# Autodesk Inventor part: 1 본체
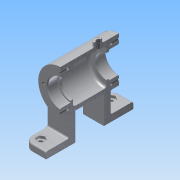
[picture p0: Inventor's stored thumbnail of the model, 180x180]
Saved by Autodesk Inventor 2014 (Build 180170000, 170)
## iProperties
Created: 2017-02
Part Number: 1 본체
Material: 알루미늄 6061
Document SubType Name: Modeling
Designer: 601-
Density: 2.71 g/cm^3
Appearance: 알루미늄 - 평지
Mass: 354.752 g
Surface Area: 426.244 cm^2
Volume: 130.905 cm^3
Author: 601-
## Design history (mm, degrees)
sketch "스케치1"
  geometry: L1 (-27, 52)-(27, 52); L2 (27, 52)-(27, -52); L3 (27, -52)-(-27, -52); L4 (-27, -52)-(-27, 52); L5 (-27, 52)-(27, -52); L6 (27, 52)-(-27, -52); L7 (-27, 17)-(27, 17); L8 (27, 17)-(27, -17); L9 (27, -17)-(-27, -17); L10 (-27, -17)-(-27, 17); L11 (-27, 17)-(27, -17); L12 (27, 17)-(-27, -17); 1 further point
  constraints: 24 end point, 4 midpoint, 4 parallel, 2 horizontal, 2 perpendicular, 1 point on line
  dimensions: "d0" = 54 distance of L1.start L1.end; "d1" = 104 distance of L1.end L2.end; "d2" = 17 distance from line of point (0, 0) L7
extrude "돌출1" new body sketch "스케치1" distance "d3" = 8; taper "d4" = 0 deg
sketch "스케치2"
  geometry: L1 (27, 0)-(-27, 0) reference; C1 r 27 at (0, 60); 1 further point
  constraints: 1 centre point, 1 vertical alignment
  dimensions: "d5" = 60 distance from line of C1.centre L1; "d6" = 54 diameter of C1
extrude "돌출2" join sketch "스케치2" stored distance "d7" = 70; taper "d8" = 0 deg
sketch "스케치3"
  geometry: L1 (27, -52)-(27, -17) reference; L2 (-27, -17)-(27, -17); L3 (27, -17)-(27, -25); L4 (27, -25)-(-27, -25); L5 (-27, -25)-(-27, -17); 1 further point
  constraints: 8 end point, 2 parallel, 1 horizontal, 1 perpendicular, 1 point on line
  dimensions: "d9" = 8 distance between parallel lines of L4 L2
extrude "돌출3" join sketch "스케치3" stored distance "d10" = 70; taper "d11" = 0 deg
node "작업 평면1"
node "작업 평면7"
sketch "스케치6"
  geometry: L1 (-35, 87)-(-35, 33) reference; L2 (-35, 87)-(35, 87) reference; L3 (-35, 60)-(-23, 60); L4 (-23, 60)-(-23, 76); L5 (-23, 76)-(-35, 76); L6 (-35, 76)-(-35, 60); L7 (-23, 60)-(-20, 60); L8 (-20, 60)-(-20, 74); L9 (-20, 74)-(-23, 74); L10 (-23, 74)-(-23, 60); L11 (-20, 60)-(20, 60); L12 (20, 60)-(20, 82); L13 (20, 82)-(-20, 82); L14 (-20, 82)-(-20, 60); L15 (20, 60)-(23, 60); L16 (23, 60)-(23, 74); L17 (23, 74)-(20, 74); L18 (20, 74)-(20, 60); L19 (23, 60)-(35, 60); L20 (35, 60)-(35, 76); L21 (35, 76)-(23, 76); L22 (23, 76)-(23, 60); 1 further point
  constraints: 40 end point, 10 parallel, 5 horizontal, 5 perpendicular, 1 midpoint
  dimensions: "d27" = 28 diameter of L17 L15; "d29" = 12 distance between parallel lines of L10 L6; "d31" = 3 distance between parallel lines of L8 L10; "d33" = 16 distance between parallel lines of L3 L5; "d34" = 14 distance between parallel lines of L7 L9; "d35" = 22 distance between parallel lines of L11 L13; "d36" = 40 distance between parallel lines of L18 L14; "d37" = 12 distance between parallel lines of L20 L16; "d38" = 16 distance between parallel lines of L19 L21; "d39" = 3 distance between parallel lines of L16 L12
revolve "회전1" sketch "스케치6" stored, may be unused: angle "d40" = 90 deg
sketch "스케치7" dims "d41" = 42
  geometry: C1 r 27 at (0, 0) reference; 3 further points
  constraints: 2 vertical alignment, 1 coincident, 2 other
hole "구멍2" sketch "스케치7" at (0, 21) diameter "d42" = 3.459; stored, may be unused: countersink angle "d46" = 90 deg, drill point angle "d48" = 118 deg; dims "d43" = 8, "d44" = 4, "d45" = 2, "d47" = 10
node "작업축1"
sketch "스케치8" dims "d52" = 42
  geometry: C1 r 16 at (0, 0) reference; C2 r 27 at (0, 0) reference; 3 further points
  constraints: 2 vertical alignment, 1 coincident, 2 other
hole "구멍3" sketch "스케치8" at (0, 21) diameter "d53" = 3.459; stored, may be unused: countersink angle "d57" = 90 deg, drill point angle "d59" = 118 deg; dims "d54" = 8, "d55" = 4, "d56" = 2, "d58" = 10
node "작업 평면2"
sketch "스케치9"
  geometry: L1 (0, 0)-(0, -27); L2 (0, 0)-(16.339, -25.16); 1 further point
  constraints: 4 end point, 1 vertical, 1 vertical alignment, 1 other
  dimensions: "d64" = 30 distance of L1.start L2.end; "d65" = 33 deg angle of L2 L1
node "작업 평면4"
node "작업 평면5"
sketch "스케치11"
  geometry: C1 r 6 at (0, 0); 1 further point
  constraints: 1 centre point
  dimensions: "d66" = 12 diameter of C1
extrude "돌출5" join sketch "스케치11" stored distance "d67" = 70; taper "d68" = 0 deg
sketch "스케치12"
  geometry: C1 r 6 at (0, 0) reference; 2 further points
  constraints: 1 coincident
hole "구멍4" sketch "스케치12" at (0, 0) diameter "d69" = 5.188; stored, may be unused: countersink angle "d73" = 90 deg, drill point angle "d75" = 118 deg; dims "d70" = 25, "d71" = 4, "d72" = 2, "d74" = 25
sketch "스케치13" dims "d78" = 9
  geometry: L1 (-12.5, -44.598)-(-17, -47.196); L2 (-17, -47.196)-(-21.5, -44.598); L3 (-21.5, -44.598)-(-21.5, -39.402); L4 (-21.5, -39.402)-(-17, -36.804); L5 (-17, -36.804)-(-12.5, -39.402); L6 (-12.5, -39.402)-(-12.5, -44.598); 4 further points
  constraints: 12 end point, 1 coincident, 1 horizontal alignment, 1 midpoint, 1 vertical alignment, 15 other
  dimensions: "d76" = 42 vertical distance of point (0, 0) point (-17, -42); "d77" = 17 horizontal distance of point (0, 0) point (-17, -42)
extrude "돌출6" cut sketch "스케치13" distance "d79" = 3; taper "d80" = 0 deg
hole "구멍5" sketch "스케치13" diameter "d81" = 5; stored, may be unused: countersink angle "d85" = 90 deg, drill point angle "d87" = 0 deg; dims "d82" = 25, "d83" = 4, "d84" = 2, "d86" = 25
fillet "모깎기1" dims "d88" = 2
fillet "모깎기2" dims "d89" = 2
fillet "모깎기3" dims "d90" = 2
fillet "모깎기4" dims "d91" = 2
fillet "모깎기5" dims "d92" = 0.3
chamfer "모따기1" distance "d94" = 1; stored, may be unused: second distance "d95" = 2, angle "d96" = 45 deg
chamfer "모따기2" distance "d97" = 1; stored, may be unused: second distance "d98" = 2, angle "d99" = 45 deg
node "작업 평면6"
sketch "스케치14"
  geometry: L1 (35, 33)-(35, 87) reference; L2 (35, 87)-(-35, 87) reference; L3 (-35, 87)-(-35, 33) reference; 2 further points
  constraints: 1 other
  dimensions: "d102" = 27 distance from line of point (0, 60) L2; "d103" = 35 distance from line of point (0, 60) L3
feature "엠보싱1" sketch "스케치14" dims "d104" = 0.5, "d105" = 0
node "작업 평면8"
sketch "스케치15"
  geometry: L1 (27, 35)-(-27, 35) reference; C1 r 5 at (0, 10); 1 further point
  constraints: 1 centre point, 1 vertical alignment
  dimensions: "d107" = 25 distance from line of C1.centre L1; "d108" = 10 diameter of C1
extrude "돌출7" join sketch "스케치15" stored distance "d109" = 10; taper "d110" = 0 deg
sketch "스케치16"
  geometry: C1 r 5 at (0, 0) reference; 2 further points
  constraints: 1 coincident
hole "구멍6" sketch "스케치16" at (0, 0) diameter "d111" = 5.188; stored, may be unused: countersink angle "d115" = 90 deg, drill point angle "d117" = 118 deg; dims "d112" = 20, "d113" = 4, "d114" = 2, "d116" = 20
fillet "모깎기8" dims "d118" = 2
fillet "모깎기9" dims "d119" = 10
fillet "모깎기10" dims "d120" = 2
fillet "모깎기11" dims "d121" = 2
fillet "모깎기12" dims "d122" = 3
node "솔리드1"
mirror "대칭1"
pattern_circular "원형 패턴1" dims angle "d50" = 360 deg
pattern_circular "원형 패턴2" dims angle "d61" = 360 deg
mirror "대칭2"
mirror "대칭3"
other parameters: "d12" = 92, "d63" = -35, "d101" = -35, "d106" = 92
